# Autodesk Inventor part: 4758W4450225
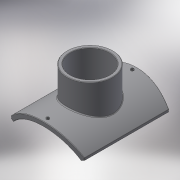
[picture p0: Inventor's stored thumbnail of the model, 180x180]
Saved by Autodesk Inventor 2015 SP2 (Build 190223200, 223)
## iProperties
Created: 2017-10
Part Number: 4758W4450225
Material: Generic
Description: PLASSON LIGHTFIT SADDLE 315-450x225 SPIGOT INLET
Document SubType Name: Modeling
Designer: KIM
Density: 1 g/cm^3
Appearance: Default
Author: KIM
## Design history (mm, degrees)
derived "4758W.ipt"
feature "Solid1::4758W.ipt"
tag "TaggingFeature1"
body "Solid1"
other parameters: "d1" = 22, "d2" = 359, "d4" = 0, "d12" = 250.6, "d13" = 14, "d14" = 207, "d16" = 5 deg, "d18" = 4, "d19" = 14, "d20" = 0, "d21" = 3, "d22" = 0, "d23" = 377, "d24" = 225, "d26" = 191.25, "d28" = 0, "d34" = 4.5, "d39" = 2.25, "d44" = 22.5, "d52" = 0, "d53" = 207, "d55" = 0, "d56" = 2.25, "d_1" = 225, "B_" = 359, "x_" = 22, "D_" = 16
